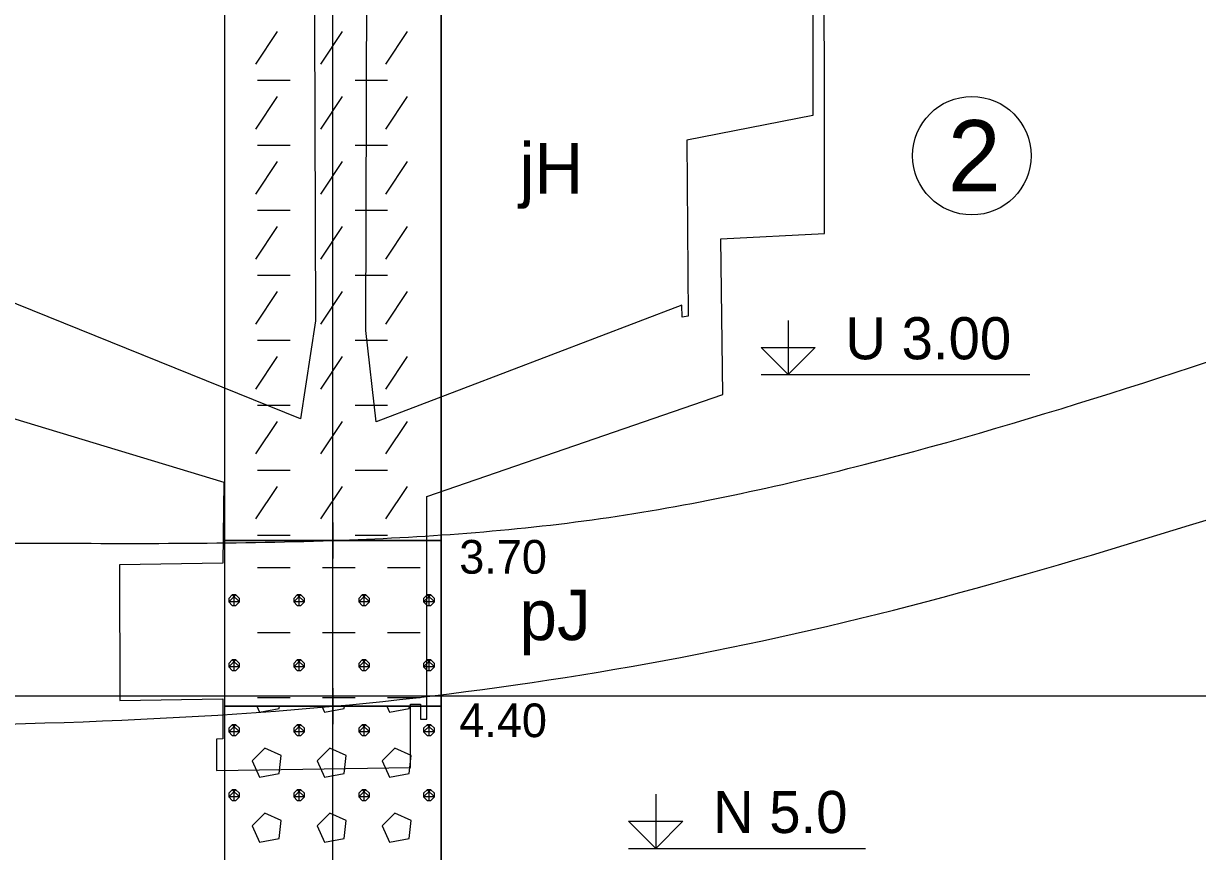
# Model space of a CAD drawing. Extents: x 3042 to 4120, y 576 to 2694.
# Drawn here: x 3330.08 to 3354.85, y 1282.78 to 1300.26 of the extents above; entities that cross this region are included whole.
import ezdxf

# ---------------------------------------------------------------- set-up
doc = ezdxf.new("R2010")
doc.units = 0
for name, color, linetype in [('18', 7, 'Continuous'), ('51', 7, 'Continuous'), ('52', 7, 'Continuous'), ('53', 7, 'Continuous'), ('56', 7, 'Continuous'), ('61', 7, 'Continuous'), ('nádrže', 7, 'Continuous'), ('rozhraní', 7, 'Continuous')]:
    doc.layers.add(name, color=color, linetype=linetype)

msp = doc.modelspace()

# ---------------------------------------------------------------- linework, layer by layer
at = {"layer": '18'}
msp.add_line((3336.607, 1272.845), (3336.607, 1307.845), dxfattribs=at)
at = {"layer": '51'}
for p, q in [((3334.98, 1299.4), (3335.437, 1300.086)), ((3336.351, 1299.4), (3336.809, 1300.086)), ((3337.723, 1299.4), (3338.18, 1300.086)), ((3335.018, 1299.058), (3335.704, 1299.058)), ((3337.075, 1299.058), (3337.761, 1299.058)), ((3334.98, 1298.029), (3335.437, 1298.715)), ((3336.351, 1298.029), (3336.809, 1298.715)), ((3337.723, 1298.029), (3338.18, 1298.715)), ((3335.018, 1297.686), (3335.704, 1297.686)), ((3337.075, 1297.686), (3337.761, 1297.686)), ((3334.98, 1296.657), (3335.437, 1297.343)), ((3336.351, 1296.657), (3336.809, 1297.343)), ((3337.723, 1296.657), (3338.18, 1297.343)), ((3335.018, 1296.314), (3335.704, 1296.314)), ((3337.075, 1296.314), (3337.761, 1296.314)), ((3334.98, 1295.286), (3335.437, 1295.971)), ((3336.351, 1295.286), (3336.809, 1295.971)), ((3337.723, 1295.286), (3338.18, 1295.971)), ((3335.018, 1294.943), (3335.704, 1294.943)), ((3337.075, 1294.943), (3337.761, 1294.943)), ((3334.98, 1293.914), (3335.437, 1294.6)), ((3336.351, 1293.914), (3336.809, 1294.6)), ((3337.723, 1293.914), (3338.18, 1294.6)), ((3335.018, 1293.571), (3335.704, 1293.571)), ((3337.075, 1293.571), (3337.761, 1293.571)), ((3334.98, 1292.542), (3335.437, 1293.228)), ((3336.351, 1292.542), (3336.809, 1293.228)), ((3337.723, 1292.542), (3338.18, 1293.228)), ((3335.018, 1292.2), (3335.704, 1292.2)), ((3337.075, 1292.2), (3337.761, 1292.2)), ((3334.98, 1291.171), (3335.437, 1291.857)), ((3336.351, 1291.171), (3336.809, 1291.857)), ((3337.723, 1291.171), (3338.18, 1291.857)), ((3335.018, 1290.828), (3335.704, 1290.828)), ((3337.075, 1290.828), (3337.761, 1290.828)), ((3334.98, 1289.799), (3335.437, 1290.485)), ((3336.351, 1289.799), (3336.809, 1290.485)), ((3337.723, 1289.799), (3338.18, 1290.485)), ((3335.018, 1289.456), (3335.704, 1289.456)), ((3337.075, 1289.456), (3337.761, 1289.456)), ((3334.523, 1289.342), (3334.523, 1289.345)), ((3335.894, 1289.342), (3335.894, 1289.345)), ((3337.266, 1289.342), (3337.266, 1289.345)), ((3338.637, 1289.342), (3338.637, 1289.345)), ((3335.018, 1288.771), (3335.704, 1288.771)), ((3336.39, 1288.771), (3337.075, 1288.771)), ((3337.761, 1288.771), (3338.447, 1288.771)), ((3334.523, 1287.97), (3334.523, 1288.199)), ((3335.894, 1287.97), (3335.894, 1288.199)), ((3337.266, 1287.97), (3337.266, 1288.199)), ((3338.637, 1287.97), (3338.637, 1288.199)), ((3335.018, 1287.399), (3335.704, 1287.399)), ((3336.39, 1287.399), (3337.075, 1287.399)), ((3337.761, 1287.399), (3338.447, 1287.399)), ((3334.523, 1286.599), (3334.523, 1286.827)), ((3335.894, 1286.599), (3335.894, 1286.827)), ((3337.266, 1286.599), (3337.266, 1286.827)), ((3338.637, 1286.599), (3338.637, 1286.827)), ((3335.018, 1286.027), (3335.704, 1286.027)), ((3336.39, 1286.027), (3337.075, 1286.027)), ((3337.761, 1286.027), (3338.447, 1286.027)), ((3334.523, 1285.227), (3334.523, 1285.456)), ((3335.894, 1285.227), (3335.894, 1285.456)), ((3337.266, 1285.227), (3337.266, 1285.456)), ((3338.637, 1285.227), (3338.637, 1285.456)), ((3334.523, 1283.856), (3334.523, 1284.084)), ((3335.894, 1283.856), (3335.894, 1284.084)), ((3337.266, 1283.856), (3337.266, 1284.084)), ((3338.637, 1283.856), (3338.637, 1284.084))]:
    msp.add_line(p, q, dxfattribs=at)
for points in [[(3334.321, 1289.345), (3338.893, 1289.345), (3338.893, 1305.345), (3334.321, 1305.345)], [(3334.321, 1285.845), (3338.893, 1285.845), (3338.893, 1289.345), (3334.321, 1289.345)], [(3334.321, 1273.845), (3338.893, 1273.845), (3338.893, 1285.845), (3334.321, 1285.845)]]:
    msp.add_lwpolyline(points, close=True, dxfattribs=at)
for points in [[(3334.481, 1289.345), (3334.485, 1289.342), (3334.561, 1289.342), (3334.564, 1289.345)], [(3335.853, 1289.345), (3335.856, 1289.342), (3335.932, 1289.342), (3335.936, 1289.345)], [(3337.224, 1289.345), (3337.228, 1289.342), (3337.304, 1289.342), (3337.307, 1289.345)], [(3338.596, 1289.345), (3338.599, 1289.342), (3338.676, 1289.342), (3338.679, 1289.345)], [(3334.485, 1288.199), (3334.408, 1288.123), (3334.408, 1288.047), (3334.485, 1287.97), (3334.561, 1287.97), (3334.637, 1288.047), (3334.637, 1288.123), (3334.561, 1288.199), (3334.485, 1288.199), (3334.637, 1288.047), (3334.408, 1288.047), (3334.561, 1288.199)], [(3335.856, 1288.199), (3335.78, 1288.123), (3335.78, 1288.047), (3335.856, 1287.97), (3335.932, 1287.97), (3336.009, 1288.047), (3336.009, 1288.123), (3335.932, 1288.199), (3335.856, 1288.199), (3336.009, 1288.047), (3335.78, 1288.047), (3335.932, 1288.199)], [(3337.228, 1288.199), (3337.152, 1288.123), (3337.152, 1288.047), (3337.228, 1287.97), (3337.304, 1287.97), (3337.38, 1288.047), (3337.38, 1288.123), (3337.304, 1288.199), (3337.228, 1288.199), (3337.38, 1288.047), (3337.152, 1288.047), (3337.304, 1288.199)], [(3338.599, 1288.199), (3338.523, 1288.123), (3338.523, 1288.047), (3338.599, 1287.97), (3338.676, 1287.97), (3338.752, 1288.047), (3338.752, 1288.123), (3338.676, 1288.199), (3338.599, 1288.199), (3338.752, 1288.047), (3338.523, 1288.047), (3338.676, 1288.199)], [(3334.485, 1286.827), (3334.408, 1286.751), (3334.408, 1286.675), (3334.485, 1286.599), (3334.561, 1286.599), (3334.637, 1286.675), (3334.637, 1286.751), (3334.561, 1286.827), (3334.485, 1286.827), (3334.637, 1286.675), (3334.408, 1286.675), (3334.561, 1286.827)], [(3335.856, 1286.827), (3335.78, 1286.751), (3335.78, 1286.675), (3335.856, 1286.599), (3335.932, 1286.599), (3336.009, 1286.675), (3336.009, 1286.751), (3335.932, 1286.827), (3335.856, 1286.827), (3336.009, 1286.675), (3335.78, 1286.675), (3335.932, 1286.827)], [(3337.228, 1286.827), (3337.152, 1286.751), (3337.152, 1286.675), (3337.228, 1286.599), (3337.304, 1286.599), (3337.38, 1286.675), (3337.38, 1286.751), (3337.304, 1286.827), (3337.228, 1286.827), (3337.38, 1286.675), (3337.152, 1286.675), (3337.304, 1286.827)], [(3338.599, 1286.827), (3338.523, 1286.751), (3338.523, 1286.675), (3338.599, 1286.599), (3338.676, 1286.599), (3338.752, 1286.675), (3338.752, 1286.751), (3338.676, 1286.827), (3338.599, 1286.827), (3338.752, 1286.675), (3338.523, 1286.675), (3338.676, 1286.827)], [(3335.001, 1285.845), (3335.056, 1285.723), (3335.475, 1285.799), (3335.48, 1285.845)], [(3336.373, 1285.845), (3336.428, 1285.723), (3336.847, 1285.799), (3336.851, 1285.845)], [(3337.745, 1285.845), (3337.799, 1285.723), (3338.218, 1285.799), (3338.223, 1285.845)], [(3334.485, 1285.456), (3334.408, 1285.38), (3334.408, 1285.303), (3334.485, 1285.227), (3334.561, 1285.227), (3334.637, 1285.303), (3334.637, 1285.38), (3334.561, 1285.456), (3334.485, 1285.456), (3334.637, 1285.303), (3334.408, 1285.303), (3334.561, 1285.456)], [(3335.856, 1285.456), (3335.78, 1285.38), (3335.78, 1285.303), (3335.856, 1285.227), (3335.932, 1285.227), (3336.009, 1285.303), (3336.009, 1285.38), (3335.932, 1285.456), (3335.856, 1285.456), (3336.009, 1285.303), (3335.78, 1285.303), (3335.932, 1285.456)], [(3337.228, 1285.456), (3337.152, 1285.38), (3337.152, 1285.303), (3337.228, 1285.227), (3337.304, 1285.227), (3337.38, 1285.303), (3337.38, 1285.38), (3337.304, 1285.456), (3337.228, 1285.456), (3337.38, 1285.303), (3337.152, 1285.303), (3337.304, 1285.456)], [(3338.599, 1285.456), (3338.523, 1285.38), (3338.523, 1285.303), (3338.599, 1285.227), (3338.676, 1285.227), (3338.752, 1285.303), (3338.752, 1285.38), (3338.676, 1285.456), (3338.599, 1285.456), (3338.752, 1285.303), (3338.523, 1285.303), (3338.676, 1285.456)], [(3334.904, 1284.694), (3335.056, 1284.351), (3335.475, 1284.427), (3335.513, 1284.808), (3335.17, 1284.961), (3334.904, 1284.694)], [(3336.275, 1284.694), (3336.428, 1284.351), (3336.847, 1284.427), (3336.885, 1284.808), (3336.542, 1284.961), (3336.275, 1284.694)], [(3337.647, 1284.694), (3337.799, 1284.351), (3338.218, 1284.427), (3338.256, 1284.808), (3337.914, 1284.961), (3337.647, 1284.694)], [(3334.485, 1284.084), (3334.408, 1284.008), (3334.408, 1283.932), (3334.485, 1283.856), (3334.561, 1283.856), (3334.637, 1283.932), (3334.637, 1284.008), (3334.561, 1284.084), (3334.485, 1284.084), (3334.637, 1283.932), (3334.408, 1283.932), (3334.561, 1284.084)], [(3335.856, 1284.084), (3335.78, 1284.008), (3335.78, 1283.932), (3335.856, 1283.856), (3335.932, 1283.856), (3336.009, 1283.932), (3336.009, 1284.008), (3335.932, 1284.084), (3335.856, 1284.084), (3336.009, 1283.932), (3335.78, 1283.932), (3335.932, 1284.084)], [(3337.228, 1284.084), (3337.152, 1284.008), (3337.152, 1283.932), (3337.228, 1283.856), (3337.304, 1283.856), (3337.38, 1283.932), (3337.38, 1284.008), (3337.304, 1284.084), (3337.228, 1284.084), (3337.38, 1283.932), (3337.152, 1283.932), (3337.304, 1284.084)], [(3338.599, 1284.084), (3338.523, 1284.008), (3338.523, 1283.932), (3338.599, 1283.856), (3338.676, 1283.856), (3338.752, 1283.932), (3338.752, 1284.008), (3338.676, 1284.084), (3338.599, 1284.084), (3338.752, 1283.932), (3338.523, 1283.932), (3338.676, 1284.084)], [(3334.904, 1283.322), (3335.056, 1282.979), (3335.475, 1283.056), (3335.513, 1283.437), (3335.17, 1283.589), (3334.904, 1283.322)], [(3336.275, 1283.322), (3336.428, 1282.979), (3336.847, 1283.056), (3336.885, 1283.437), (3336.542, 1283.589), (3336.275, 1283.322)], [(3337.647, 1283.322), (3337.799, 1282.979), (3338.218, 1283.056), (3338.256, 1283.437), (3337.914, 1283.589), (3337.647, 1283.322)]]:
    msp.add_lwpolyline(points, dxfattribs=at)
at = {"layer": '53'}
for p, q in [((3334.321, 1307.845), (3334.321, 1272.845)), ((3338.893, 1307.845), (3338.893, 1272.845)), ((3334.321, 1289.345), (3338.893, 1289.345)), ((3334.321, 1285.845), (3338.893, 1285.845))]:
    msp.add_line(p, q, dxfattribs=at)
at = {"layer": '56'}
for p, q in [((3336.607, 1289.726), (3336.607, 1288.964)), ((3336.226, 1289.345), (3336.988, 1289.345)), ((3336.607, 1286.226), (3336.607, 1285.464)), ((3336.226, 1285.845), (3336.988, 1285.845))]:
    msp.add_line(p, q, dxfattribs=at)
at = {"layer": '61'}
for p, q in [((3345.643, 1292.845), (3351.316, 1292.845)), ((3342.849, 1282.845), (3347.845, 1282.845))]:
    msp.add_line(p, q, dxfattribs=at)
for points in [[(3346.215, 1293.988), (3346.215, 1292.845), (3345.643, 1293.417), (3346.786, 1293.417), (3346.215, 1292.845)], [(3343.421, 1283.988), (3343.421, 1282.845), (3342.849, 1283.417), (3343.992, 1283.417), (3343.421, 1282.845)]]:
    msp.add_lwpolyline(points, dxfattribs=at)
at = {"layer": 'nádrže'}
for points in [[(3326.402, 1310.876), (3326.507, 1295.974), (3328.606, 1295.974), (3328.606, 1292.302), (3334.303, 1290.575), (3334.282, 1288.866), (3332.107, 1288.833), (3332.108, 1285.97), (3334.284, 1286.003), (3334.285, 1285.155), (3334.152, 1285.153), (3334.152, 1284.49), (3338.247, 1284.553), (3338.246, 1285.89), (3338.456, 1285.893), (3338.456, 1285.573), (3338.59, 1285.576), (3338.587, 1290.27), (3344.838, 1292.426), (3344.793, 1295.711), (3346.984, 1295.824), (3346.966, 1312.095)], [(3336.182, 1310.814), (3336.241, 1293.984), (3335.922, 1291.915), (3329.271, 1294.601), (3329.26, 1297.659), (3326.749, 1298.45), (3326.647, 1311.014)], [(3346.721, 1310.867), (3346.735, 1298.315), (3344.079, 1297.798), (3344.108, 1294.081), (3343.977, 1294.055), (3343.975, 1294.312), (3337.524, 1291.848), (3337.306, 1293.777), (3337.35, 1310.875)]]:
    msp.add_lwpolyline(points, dxfattribs=at)
at = {"layer": 'rozhraní'}
for p, q in [((3317.941, 1289.19), (3330.077, 1289.291)), ((3432.629, 1286.055), (3323.661, 1286.055))]:
    msp.add_line(p, q, dxfattribs=at)
msp.add_circle((3350.093, 1297.467), 1.25, dxfattribs=at)
for points in [[(3215.367, 1295.492), (3223.007, 1295.445), (3284.237, 1298.745), (3466.926, 1305.295), (3469.69, 1305.295), (3507.357, 1301.345), (3560.04, 1300.995)], [(3330.077, 1289.291), (3336.607, 1289.345), (3342.253, 1289.807), (3347.822, 1290.949), (3358.825, 1294.38), (3369.814, 1297.856), (3375.365, 1299.054), (3380.987, 1299.595), (3385.695, 1299.64), (3390.406, 1299.619), (3399.821, 1299.325), (3409.251, 1298.784), (3418.647, 1298.095), (3424.692, 1297.433), (3430.738, 1296.484), (3442.828, 1294.299), (3448.859, 1293.371), (3451.886, 1292.998), (3454.918, 1292.687), (3460.963, 1292.471), (3467.007, 1292.795), (3475.291, 1293.755), (3483.553, 1294.967), (3491.821, 1296.12), (3500.124, 1296.9), (3507.357, 1297.345)], [(3271.345, 1282.999), (3284.237, 1284.245), (3297.343, 1284.894), (3310.501, 1285.162), (3323.62, 1285.371), (3336.607, 1285.845), (3347.74, 1287.702), (3358.827, 1290.97), (3369.9, 1294.05), (3375.439, 1295.021), (3378.212, 1295.276), (3380.987, 1295.345), (3390.374, 1294.201), (3399.75, 1291.756), (3409.16, 1289.169), (3418.647, 1287.595), (3430.693, 1286.786), (3442.786, 1286.102), (3454.9, 1285.59), (3467.007, 1285.295), (3487.184, 1285.301), (3497.273, 1285.651), (3507.357, 1286.345), (3512.194, 1287.141), (3526.536, 1295.496), (3547.897, 1291.945), (3557.186, 1291.945)]]:
    msp.add_spline(points, degree=3, dxfattribs=at)

# ---------------------------------------------------------------- texts
at = {"layer": '52'}
for s, height, p in [('jH', 1.0668, (3340.544, 1296.667)), ('3.70', 0.7112, (3339.274, 1288.644)), ('pJ', 1.0668, (3340.544, 1287.241)), ('4.40', 0.7112, (3339.274, 1285.193))]:
    msp.add_text(s, height=height, dxfattribs=at).set_placement(p)
at = {"layer": '61'}
for s, p in [('U 3.00', (3347.421, 1293.169)), ('N 5.0', (3344.627, 1283.169))]:
    msp.add_text(s, height=0.889, dxfattribs=at).set_placement(p)
at = {"layer": 'rozhraní'}
msp.add_text('2', height=1.5, dxfattribs=at).set_placement((3349.585, 1296.717))

doc.saveas('drawing.dxf')
